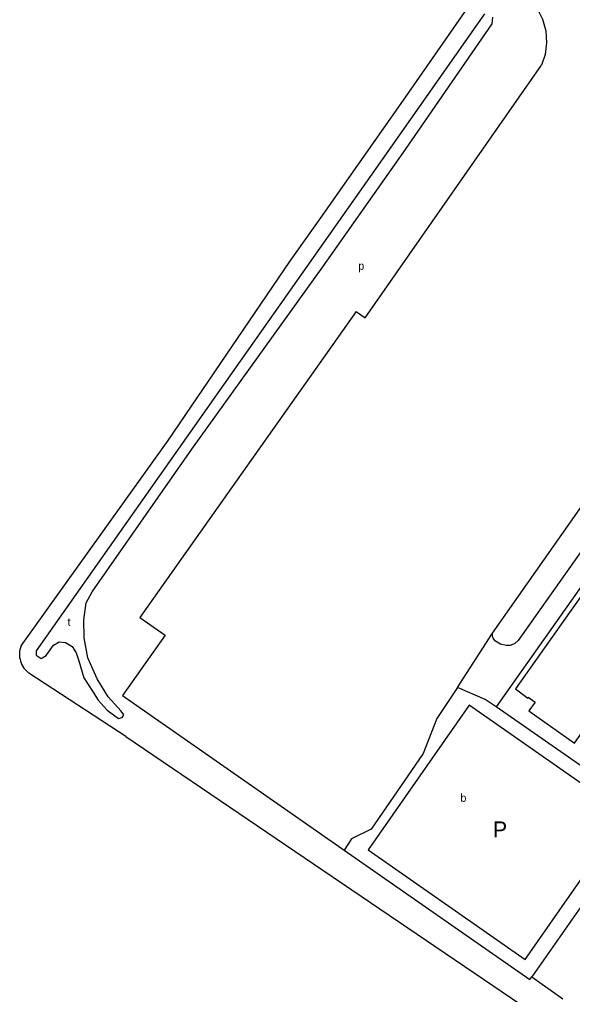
# Model space of a CAD drawing. Extents: x 154765 to 156627, y 383996 to 386132.
# Drawn here: x 154764.9 to 155041.5, y 384927.3 to 385414.8 of the extents above; entities that cross this region are included whole.
import ezdxf

# ---------------------------------------------------------------- set-up
doc = ezdxf.new("R2010")
doc.units = 0
for name, color, linetype in [('BLT_Basislijn', 7, 'Continuous'), ('BLT_Bebouwing', 7, 'Continuous'), ('BLT_Centroide', 7, 'Continuous'), ('BLT_Tekst_parkeren', 7, 'Continuous')]:
    doc.layers.add(name, color=color, linetype=linetype)

msp = doc.modelspace()

# ---------------------------------------------------------------- linework, layer by layer
at = {"layer": 'BLT_Basislijn'}
for p, q in [((154983.96, 385080.91), (155001.53, 385107.93)), ((154818, 385056.39), (154769.57, 385088.04)), ((155065.31, 385027.95), (155003.26, 385071.14)), ((154818, 385056.39), (155015.72, 384922.31)), ((155065.97, 385000.42), (155021.15, 384936.15)), ((154927.31, 384999.55), (155020.19, 384934.78)), ((155020.19, 384934.78), (155021.15, 384936.15)), ((155021.15, 384936.15), (155036.67, 384925.21))]:
    msp.add_line(p, q, dxfattribs=at)
for points in [[(155001.53, 385107.93), (155095.72, 385242.01), (155221.63, 385421.26), (155278.06, 385501.59), (155307.92, 385531.59), (155362.73, 385609.97), (155374.64, 385636.58)], [(154765.62, 385101.6), (154839.26, 385204.33), (154900.05, 385293.83), (154915.63, 385315.65), (154956.88, 385374.58), (155001.95, 385439.41)], [(155015.95, 385428.47), (155020.19, 385424.88), (155023.84, 385420.32), (155026.58, 385414.96), (155028.2, 385409.1), (155028.58, 385403.09), (155027.78, 385397.3), (155025.98, 385392.05)], [(154997.48, 385417.61), (154946.23, 385344.88), (154920.16, 385307.59), (154773.16, 385099.14), (154773.17, 385096.99), (154775.64, 385095.35), (154778.2, 385096.9), (154781.94, 385101.93), (154784.69, 385103.75), (154787.88, 385103.39), (154791.26, 385101.38), (154793.27, 385098.18), (154794.46, 385094.16), (154797.02, 385085.66), (154801.41, 385079.08), (154804.15, 385074.52), (154808.72, 385069.49), (154814.38, 385065.29), (154816.3, 385065.84), (154817.12, 385067.11), (154815.75, 385069.03), (154809.17, 385076.25), (154803.69, 385085.21), (154799.03, 385095.62), (154797.29, 385105.67), (154797.02, 385114.63), (154798.21, 385123.12), (154801.13, 385128.7), (154851.11, 385199.97), (154916.62, 385291.24), (154957.92, 385349.9), (155001.32, 385412.67), (155001.59, 385415.96)], [(155234.74, 385412.07), (155228.58, 385403.41), (155224.55, 385391.47), (155216.21, 385379.72), (155192.97, 385359.25), (155123.67, 385259.51), (155043.61, 385145.9), (155014.37, 385104.41), (155012.61, 385102.8), (155010.41, 385101.87), (155008.28, 385101.81), (155005.41, 385102.5), (155003.02, 385104.02), (155002.04, 385105.22), (155001.66, 385106.08), (155001.51, 385106.85), (155001.53, 385107.93)], [(154933.35, 385268.89), (154937.81, 385265.73), (155025.98, 385392.05)], [(154933.35, 385268.89), (154825.09, 385115.9), (154837.72, 385106.96), (154816.43, 385076.87)], [(155108.39, 385219.41), (155090.89, 385194.93), (155003.26, 385071.14)], [(154765.62, 385101.6), (154765.32, 385100.68), (154765.08, 385099.75), (154764.93, 385098.8), (154764.85, 385097.83), (154764.86, 385096.87), (154764.94, 385095.91), (154765.11, 385094.96), (154765.35, 385094.02), (154765.67, 385093.11), (154766.06, 385092.23), (154766.53, 385091.38), (154767.06, 385090.58), (154767.66, 385089.82), (154768.32, 385089.12), (154769.03, 385088.47), (154769.57, 385088.04)], [(154983.96, 385080.91), (154973.62, 385065.31), (154966.8, 385047.88), (154940.78, 385010.04), (154930.88, 385005.12), (154927.31, 384999.55)], [(155003.26, 385071.14), (154997.83, 385074.91), (154983.96, 385080.91)], [(154816.43, 385076.87), (154922.83, 385002.67), (154927.31, 384999.55)]]:
    msp.add_lwpolyline(points, dxfattribs=at)
at = {"layer": 'BLT_Bebouwing'}
for points in [[(155057.14, 385128.56), (155050.59, 385133.21), (155012.92, 385080.15), (155019.1, 385075.56), (155019.4, 385075.98), (155022.81, 385073.57), (155019.67, 385069.15), (155042.45, 385052.95), (155046.36, 385058.44)], [(154989.77, 385071.98), (154939.28, 384999.74), (155017.82, 384944.9), (155068.35, 385017.24), (154989.77, 385071.98)]]:
    msp.add_lwpolyline(points, dxfattribs=at)

# ---------------------------------------------------------------- texts
at = {"layer": 'BLT_Centroide'}
for s, p in [('p', (154934.36, 385289.66)), ('t', (154788.91, 385111.62)), ('b', (154985.43, 385023.68))]:
    msp.add_text(s, height=4, dxfattribs=at).set_placement(p)
at = {"layer": 'BLT_Tekst_parkeren'}
msp.add_text('P', height=8, rotation=359.9654, dxfattribs=at).set_placement((155001.65, 385005.86))

doc.saveas('drawing.dxf')
